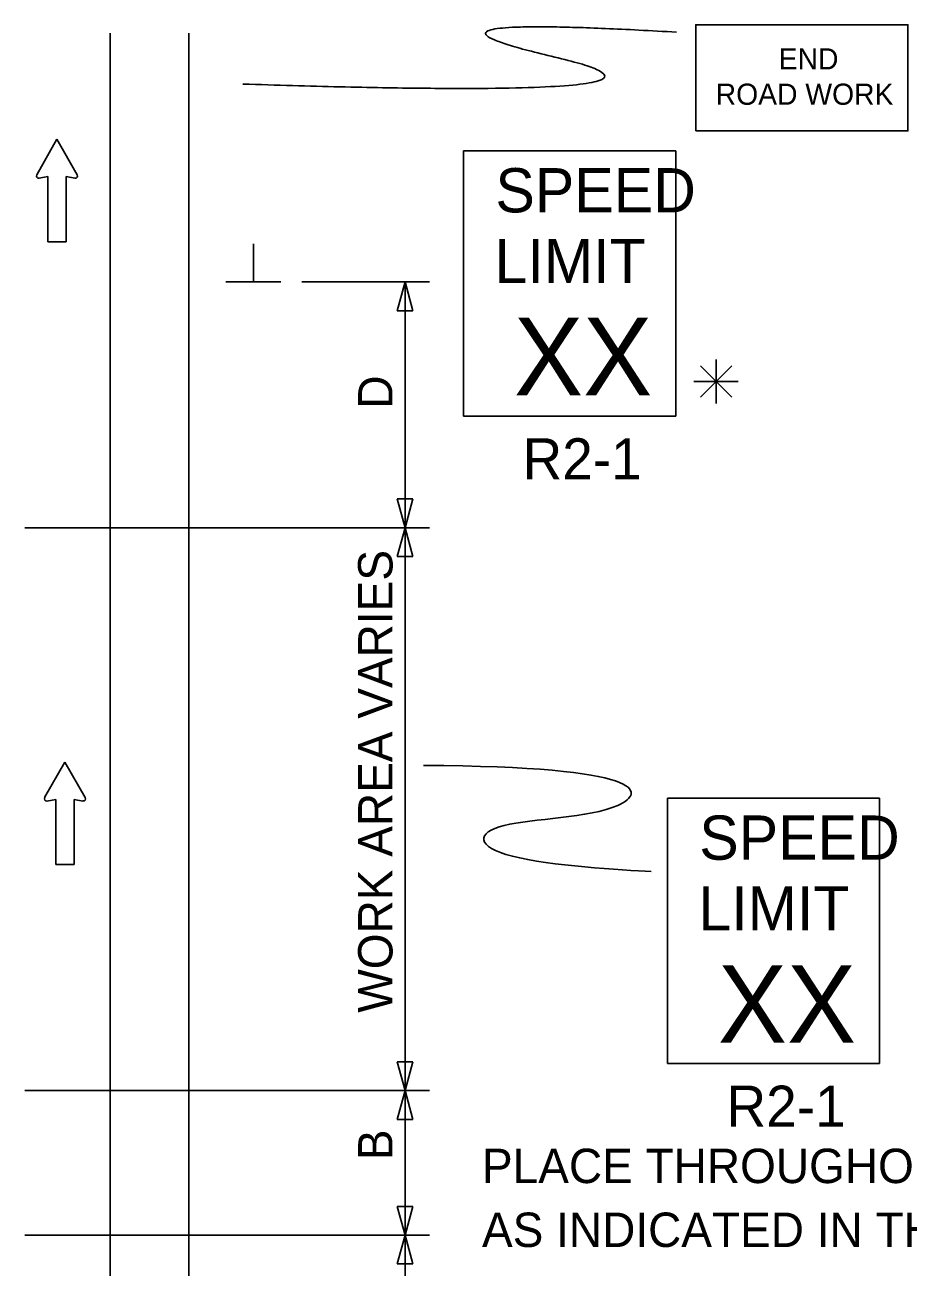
# Model space of a CAD drawing. Extents: x 16503 to 19508, y 5728 to 6974.
# Drawn here: x 18016.2 to 18196, y 6670.3 to 6923 of the extents above; entities that cross this region are included whole.
import ezdxf

# ---------------------------------------------------------------- set-up
doc = ezdxf.new("R2010")
doc.units = 0
for name, color, linetype in [('MT_SCRATCH_LEVEL_E', 7, 'Continuous'), ('PAVT_EDGE_EX', 7, 'Continuous'), ('TRAFFIC_SIGNS_PR', 7, 'Continuous'), ('TYPICAL_TEXT_DIMEN_PR', 7, 'Continuous')]:
    doc.layers.add(name, color=color, linetype=linetype)

msp = doc.modelspace()

# ---------------------------------------------------------------- linework, layer by layer
at = {"layer": 'MT_SCRATCH_LEVEL_E'}
for p, q in [((18022.77, 6899.76), (18018.65, 6892.52)), ((18026.91, 6892.52), (18022.77, 6899.76)), ((18019.14, 6891.84), (18020.91, 6892.15)), ((18020.91, 6892.15), (18020.91, 6878.9)), ((18024.66, 6878.9), (18024.66, 6892.15)), ((18024.66, 6892.15), (18026.43, 6891.84)), ((18020.91, 6878.9), (18024.66, 6878.9)), ((18024.38, 6773.03), (18020.27, 6765.79)), ((18028.53, 6765.79), (18024.38, 6773.03)), ((18020.75, 6765.1), (18022.53, 6765.42)), ((18022.53, 6765.42), (18022.53, 6752.16)), ((18026.27, 6752.16), (18026.27, 6765.42)), ((18026.27, 6765.42), (18028.05, 6765.1)), ((18022.53, 6752.16), (18026.27, 6752.16))]:
    msp.add_line(p, q, dxfattribs=at)
for centre, start, end in [((18019.06, 6892.3), 150.4248, 279.9638), ((18026.5, 6892.3), 260.0362, 29.7731), ((18020.68, 6765.56), 150.4248, 279.9638), ((18028.12, 6765.57), 260.0362, 29.7731)]:
    msp.add_arc(centre, 0.463, start, end, dxfattribs=at)
at = {"layer": 'PAVT_EDGE_EX'}
for p, q in [((18033.63, 6921.33), (18033.63, 5988.51)), ((18049.63, 6921.33), (18049.63, 5988.51))]:
    msp.add_line(p, q, dxfattribs=at)
at = {"layer": 'TRAFFIC_SIGNS_PR'}
for p, q in [((18105.54, 6897.41), (18148.74, 6897.41)), ((18105.54, 6843.41), (18105.54, 6897.41)), ((18148.74, 6843.41), (18148.74, 6897.41)), ((18105.54, 6843.41), (18148.74, 6843.41)), ((18147.04, 6765.69), (18190.24, 6765.69)), ((18147.04, 6711.69), (18147.04, 6765.69)), ((18190.24, 6711.69), (18190.24, 6765.69)), ((18147.04, 6711.69), (18190.24, 6711.69))]:
    msp.add_line(p, q, dxfattribs=at)
msp.add_lwpolyline([(18152.81, 6901.44), (18196.01, 6901.44), (18196.01, 6923.04), (18152.81, 6923.04)], close=True, dxfattribs=at)
msp.add_open_spline([(18148.92, 6921.54), (18086.6, 6925.24), (18161.65, 6907.71), (18060.63, 6910.98)], degree=2, dxfattribs=at)
at = {"layer": 'TYPICAL_TEXT_DIMEN_PR'}
for p, q in [((18062.76, 6870.72), (18062.76, 6878.51)), ((18068.38, 6870.72), (18057.13, 6870.72)), ((18098.63, 6870.72), (18072.63, 6870.72)), ((18092.06, 6864.86), (18093.63, 6870.72)), ((18093.63, 6870.72), (18093.63, 6820.72)), ((18093.63, 6870.72), (18095.2, 6864.86)), ((18093.63, 6864.86), (18092.06, 6864.86)), ((18095.2, 6864.86), (18093.63, 6864.86)), ((18153.78, 6853.65), (18160.15, 6847.28)), ((18160.15, 6853.65), (18153.78, 6847.28)), ((18156.97, 6850.47), (18156.97, 6854.92)), ((18156.97, 6850.47), (18152.43, 6850.47)), ((18156.97, 6850.47), (18160.15, 6850.47)), ((18156.97, 6850.47), (18161.44, 6850.47)), ((18156.97, 6850.47), (18156.97, 6845.97)), ((18093.63, 6820.72), (18092.06, 6826.58)), ((18092.06, 6826.58), (18093.63, 6826.58)), ((18093.63, 6826.58), (18095.2, 6826.58)), ((18095.2, 6826.58), (18093.63, 6820.72)), ((18098.63, 6820.72), (18016.24, 6820.72)), ((18092.06, 6814.86), (18093.63, 6820.72)), ((18093.63, 6706.19), (18093.63, 6820.72)), ((18093.63, 6820.72), (18095.2, 6814.86)), ((18093.63, 6814.86), (18092.06, 6814.86)), ((18095.2, 6814.86), (18093.63, 6814.86)), ((18093.63, 6706.19), (18092.06, 6712.05)), ((18092.06, 6712.05), (18093.63, 6712.05)), ((18093.63, 6712.05), (18095.2, 6712.05)), ((18095.2, 6712.05), (18093.63, 6706.19)), ((18098.63, 6706.19), (18016.24, 6706.19)), ((18092.06, 6700.32), (18093.63, 6706.19)), ((18093.63, 6676.76), (18093.63, 6706.19)), ((18093.63, 6706.19), (18095.2, 6700.32)), ((18093.63, 6700.32), (18092.06, 6700.32)), ((18095.2, 6700.32), (18093.63, 6700.32)), ((18093.63, 6676.76), (18092.06, 6682.62)), ((18092.06, 6682.62), (18093.63, 6682.62)), ((18093.63, 6682.62), (18095.2, 6682.62)), ((18095.2, 6682.62), (18093.63, 6676.76)), ((18098.63, 6676.76), (18016.24, 6676.76)), ((18092.06, 6670.9), (18093.63, 6676.76)), ((18093.63, 6646.19), (18093.63, 6676.76)), ((18093.63, 6676.76), (18095.2, 6670.9)), ((18093.63, 6670.9), (18092.06, 6670.9)), ((18095.2, 6670.9), (18093.63, 6670.9))]:
    msp.add_line(p, q, dxfattribs=at)
msp.add_open_spline([(18097.36, 6772.34), (18142.93, 6772.13), (18142.7, 6761.59), (18108.02, 6761.59), (18108.02, 6752.88), (18137.88, 6751.02), (18143.74, 6750.76)], degree=3, dxfattribs=at)

# ---------------------------------------------------------------- texts
at = {"layer": 'TRAFFIC_SIGNS_PR'}
for s, height, p in [('END', 4.31, (18169.69, 6913.96)), ('ROAD WORK', 4.31, (18156.87, 6906.77)), ('SPEED', 9, (18112.03, 6884.88)), ('LIMIT', 9, (18111.85, 6870.48)), ('XX', 15.785, (18115.8, 6847.64)), ('R2-1', 8.37, (18117.55, 6830.54)), ('SPEED', 9, (18153.53, 6753.16)), ('LIMIT', 9, (18153.35, 6738.76)), ('XX', 15.785, (18157.3, 6715.91)), ('R2-1', 8.37, (18159.06, 6698.82)), ('PLACE THROUGHOUT WORK AREA', 7, (18109.3, 6687.36)), ('AS INDICATED IN THE NOTES.', 7, (18109.3, 6674.36))]:
    msp.add_text(s, height=height, dxfattribs=at).set_placement(p)
at = {"layer": 'TYPICAL_TEXT_DIMEN_PR'}
for s, p in [('D', (18091.08, 6844.94)), ('WORK AREA VARIES', (18091.08, 6722.04)), ('B', (18091.08, 6692.02))]:
    msp.add_text(s, height=7, rotation=90, dxfattribs=at).set_placement(p)

doc.saveas('drawing.dxf')
